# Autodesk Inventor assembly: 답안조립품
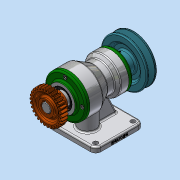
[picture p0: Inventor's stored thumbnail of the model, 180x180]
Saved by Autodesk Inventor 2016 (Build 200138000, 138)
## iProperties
Created: 2019-01
Part Number: 답안조립품
Document SubType Name: Assembly
Designer: MIRAE
Author: MIRAE
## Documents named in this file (15)
- C:\Users\MIRAE\Desktop\490108V1004\답안조립품.iam
- C:\Users\MIRAE\Desktop\490108V1004\본체.ipt
- C:\Users\MIRAE\Desktop\490108V1004\축.ipt
- C:\Users\MIRAE\Desktop\490108V1004\키 6 x 6 x 18.ipt
- C:\Users\MIRAE\Desktop\490108V1004\멈춤나사 M3.ipt
- C:\Users\MIRAE\Desktop\490108V1004\스퍼기어.ipt
- C:\Users\MIRAE\Desktop\490108V1004\베어링 6205.ipt
- C:\Users\MIRAE\Desktop\490108V1004\앞커버.ipt
- C:\Users\MIRAE\Desktop\490108V1004\오일 실 25 38 8.ipt
- C:\Users\MIRAE\Desktop\490108V1004\볼트 M4.ipt
- C:\Users\MIRAE\Desktop\490108V1004\베어링 6203.ipt
- C:\Users\MIRAE\Desktop\490108V1004\뒤커버.ipt
- C:\Users\MIRAE\Desktop\490108V1004\오일 실 17 30 8.ipt
- C:\Users\MIRAE\Desktop\490108V1004\키 5 x 5 x 20.ipt
- C:\Users\MIRAE\Desktop\490108V1004\V-벨트풀리.ipt
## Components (1 placed, 1 different names)
1. V-벨트풀리:1
